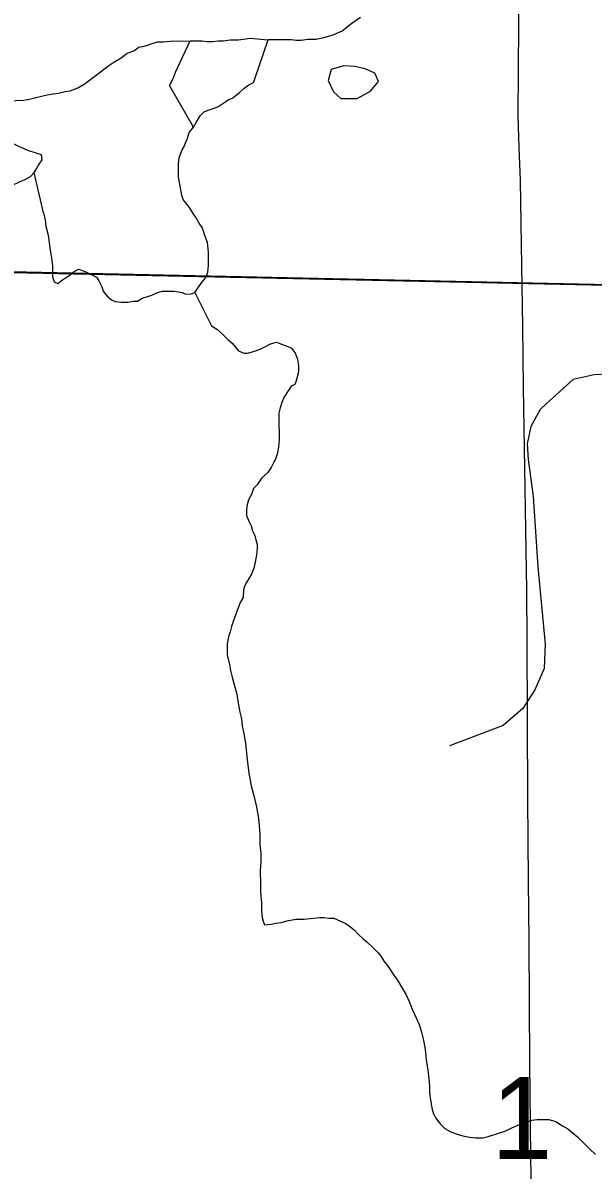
# Model space of a CAD drawing. Extents: x -6.1 to 38, y -7.7 to 22.
# Drawn here: x 2.439 to 2.73, y 14.598 to 15.183 of the extents above; entities that cross this region are included whole.
import ezdxf

# ---------------------------------------------------------------- set-up
doc = ezdxf.new("R2010")
doc.units = 0
for name, color, linetype in [('GM_X_Corporation', 7, 'Continuous'), ('GM_X_Major_River', 7, 'Continuous'), ('GM_X_Minor_Lake', 7, 'Continuous'), ('GM_X_Minor_River', 7, 'Continuous'), ('GM_X_Section_Text', 7, 'Continuous'), ('GM_X_Township_Road', 7, 'Continuous')]:
    doc.layers.add(name, color=color, linetype=linetype)

msp = doc.modelspace()

# ---------------------------------------------------------------- linework, layer by layer
at = {"layer": 'GM_X_Corporation'}
msp.add_lwpolyline([(2.1, 20.09414), (2.1, 15.06368), (2.27273, 15.0594), (2.84159, 15.04746)], dxfattribs=at)
for points in [[(2.23638, 16.06946), (3.24267, 16.03673), (3.24072, 15.94663), (3.23485, 15.60898), (3.22944, 15.30622), (3.22502, 15.03923), (2.22108, 15.06099)], [(2.1, 15.06368), (2.1, 14.1), (3.19219, 14.1), (3.19363, 14.14313), (3.20818, 14.53184), (3.22164, 14.89402), (3.22473, 15.03847), (3.13213, 15.04149), (2.88274, 15.0466), (2.84159, 15.04746), (2.27273, 15.0594)], [(2.22108, 15.06099), (3.22502, 15.03923), (3.195, 14.20385), (2.1728, 14.23687), (2.18735, 15.06192)]]:
    msp.add_lwpolyline(points, close=True, dxfattribs=at)
at = {"layer": 'GM_X_Major_River'}
for points in [[(2.61162, 15.18627), (2.6071, 15.18318), (2.6022, 15.17933), (2.5969, 15.177), (2.59274, 15.17581), (2.58894, 15.17501), (2.58476, 15.17497), (2.58134, 15.17456), (2.57868, 15.17453), (2.5764, 15.17489), (2.57412, 15.17487), (2.5707, 15.17483)], [(2.43155, 15.14368), (2.4395, 15.14411), (2.44253, 15.14451), (2.44518, 15.14529), (2.44858, 15.14607), (2.45161, 15.14685), (2.45464, 15.14725), (2.45729, 15.14765), (2.46069, 15.14843), (2.46334, 15.14883), (2.46712, 15.15037), (2.47051, 15.15229), (2.47315, 15.15421), (2.47654, 15.15688), (2.48257, 15.16148), (2.48559, 15.1634), (2.48936, 15.1657), (2.49238, 15.168), (2.49578, 15.16916), (2.49842, 15.17108), (2.50182, 15.17186), (2.50523, 15.17302), (2.50787, 15.1738), (2.5109, 15.17382), (2.51431, 15.17422), (2.52454, 15.17429), (2.52719, 15.17431), (2.5306, 15.17433), (2.53326, 15.17397), (2.53591, 15.17399), (2.53894, 15.17439), (2.54159, 15.17441), (2.545, 15.17481), (2.54916, 15.17484), (2.55181, 15.17524), (2.55522, 15.17564), (2.56436, 15.17477)], [(2.5707, 15.17483), (2.56766, 15.1748), (2.56436, 15.17477)]]:
    msp.add_lwpolyline(points, dxfattribs=at)
at = {"layer": 'GM_X_Minor_Lake'}
msp.add_line((2.60875, 15.16122), (2.60308, 15.16162), dxfattribs=at)
msp.add_lwpolyline([(2.60308, 15.16162), (2.59664, 15.15974), (2.59512, 15.15406), (2.59775, 15.14836), (2.60152, 15.14494), (2.60984, 15.14491), (2.61665, 15.14868), (2.62083, 15.1536), (2.61895, 15.15777), (2.61404, 15.16006), (2.60875, 15.16122)], dxfattribs=at)
at = {"layer": 'GM_X_Minor_River'}
for points in [[(2.44969, 15.08656), (2.4505, 15.08277), (2.45091, 15.07973), (2.45211, 15.07518), (2.45294, 15.06873), (2.45376, 15.06341), (2.45419, 15.05923), (2.45423, 15.05619), (2.45425, 15.05391), (2.45504, 15.05126), (2.45695, 15.05052), (2.45959, 15.05244), (2.46261, 15.05437), (2.46487, 15.0563), (2.46751, 15.05784), (2.47133, 15.05636), (2.47439, 15.05487), (2.47668, 15.05376), (2.47785, 15.05187), (2.4794, 15.04884), (2.48019, 15.04656), (2.48212, 15.04392), (2.48442, 15.04204), (2.48633, 15.0413), (2.48938, 15.04095), (2.4928, 15.04099), (2.49545, 15.0414), (2.49773, 15.04142), (2.5, 15.04296), (2.50492, 15.04453), (2.50757, 15.0457), (2.51022, 15.04648), (2.51402, 15.04652), (2.5163, 15.04654), (2.51859, 15.04619), (2.52049, 15.04583), (2.5224, 15.04508), (2.52506, 15.04511), (2.52695, 15.04589), (2.53032, 15.05087), (2.53257, 15.05355), (2.53368, 15.05622), (2.53402, 15.05965), (2.53397, 15.06345), (2.53394, 15.06649), (2.5335, 15.07143), (2.53232, 15.07446), (2.53154, 15.07673), (2.53075, 15.07901), (2.52921, 15.08127), (2.52765, 15.08392), (2.52611, 15.08618), (2.52456, 15.08883), (2.52301, 15.09071), (2.52108, 15.09336), (2.52029, 15.09563), (2.51867, 15.10474), (2.51863, 15.10778), (2.51859, 15.11158), (2.51893, 15.11463), (2.51967, 15.11654), (2.52041, 15.11844), (2.52153, 15.12036), (2.52227, 15.12226), (2.52301, 15.12417), (2.52411, 15.12761), (2.52636, 15.13029), (2.52785, 15.13297), (2.52971, 15.13602), (2.53197, 15.13833), (2.53537, 15.1395), (2.53878, 15.14068), (2.5418, 15.14261), (2.54406, 15.14415), (2.54633, 15.14531), (2.54972, 15.14801), (2.55198, 15.14994), (2.55462, 15.15186), (2.55689, 15.15302), (2.55762, 15.15493), (2.56436, 15.17477)], [(2.51395, 15.15146), (2.51507, 15.15337), (2.51617, 15.15604), (2.51728, 15.15871), (2.52454, 15.17429)], [(2.52636, 15.13029), (2.51395, 15.15146)], [(2.4127, 15.09646), (2.4165, 15.0965), (2.4203, 15.09692), (2.4241, 15.09733), (2.42826, 15.0989), (2.43357, 15.10047), (2.43734, 15.10241), (2.44037, 15.10358), (2.44301, 15.10513), (2.44489, 15.10705), (2.44601, 15.10896), (2.44713, 15.11087), (2.449, 15.11355), (2.44859, 15.11621), (2.44592, 15.11694), (2.44172, 15.11842), (2.43675, 15.12065), (2.43293, 15.12252), (2.43025, 15.12401), (2.42793, 15.12779), (2.4279, 15.12969), (2.42788, 15.13159), (2.4289, 15.14252)], [(2.44969, 15.08656), (2.44489, 15.10705)], [(2.52695, 15.04589), (2.53552, 15.02887), (2.53858, 15.027), (2.54127, 15.02436), (2.54396, 15.02172), (2.54626, 15.01985), (2.54781, 15.01796), (2.54935, 15.01608), (2.55202, 15.01496), (2.55392, 15.01498), (2.55696, 15.01577), (2.56036, 15.01695), (2.56339, 15.0185), (2.56565, 15.01966), (2.56868, 15.02045), (2.57174, 15.01934), (2.57441, 15.01822), (2.57632, 15.01749), (2.57825, 15.01484), (2.57943, 15.01181), (2.57985, 15.0084), (2.57989, 15.00536), (2.5788, 15.00078), (2.57806, 14.99887), (2.57617, 14.99809), (2.57505, 14.99618), (2.57243, 14.99235), (2.57132, 14.98968), (2.57059, 14.98701), (2.56986, 14.98434), (2.5699, 14.9813), (2.56993, 14.97826), (2.56998, 14.97446), (2.57002, 14.97104), (2.56969, 14.96685), (2.56897, 14.96342), (2.56824, 14.96076), (2.56712, 14.95884), (2.566, 14.95655), (2.56414, 14.95387), (2.56113, 14.95118), (2.55888, 14.94774), (2.557, 14.94581), (2.5559, 14.94276), (2.55441, 14.94009), (2.55368, 14.93742), (2.55333, 14.93513), (2.55336, 14.93209), (2.55454, 14.92906), (2.55571, 14.92679), (2.5565, 14.92414), (2.55766, 14.92187), (2.55807, 14.91959), (2.55886, 14.91732), (2.55888, 14.91542), (2.55854, 14.91199), (2.55782, 14.90818), (2.5571, 14.90513), (2.55599, 14.90208), (2.5545, 14.89979), (2.55338, 14.89787), (2.55226, 14.89596), (2.5519, 14.89406), (2.55157, 14.89025), (2.55008, 14.88758), (2.54676, 14.87842), (2.54566, 14.87536), (2.54493, 14.8727), (2.5442, 14.87003), (2.54348, 14.8666), (2.54352, 14.86318), (2.54354, 14.8609), (2.54395, 14.85862), (2.54474, 14.85597), (2.54516, 14.85293), (2.54596, 14.84951), (2.54714, 14.84572), (2.54834, 14.84079), (2.54915, 14.83624), (2.54997, 14.83169), (2.55077, 14.82827), (2.55119, 14.82447), (2.55199, 14.82068), (2.55281, 14.81574), (2.55367, 14.80739), (2.55451, 14.80055), (2.55572, 14.7941), (2.55731, 14.78841), (2.55851, 14.7831), (2.55932, 14.77855), (2.55976, 14.77399), (2.56019, 14.76905), (2.56025, 14.76411), (2.56068, 14.75955), (2.56073, 14.75537), (2.56041, 14.75043), (2.56049, 14.74396), (2.56054, 14.7394), (2.56097, 14.73446), (2.56103, 14.7299), (2.56144, 14.72686)], [(2.56144, 14.72686), (2.56185, 14.72497), (2.56263, 14.72307), (2.56604, 14.72349), (2.56832, 14.72389), (2.57098, 14.7243), (2.57401, 14.72508), (2.57856, 14.72589), (2.58274, 14.72593), (2.59072, 14.72677), (2.593, 14.72679), (2.59566, 14.72644), (2.59794, 14.72647), (2.60138, 14.72498), (2.60368, 14.72386), (2.60597, 14.72236), (2.60828, 14.72048), (2.61058, 14.71822), (2.61289, 14.71597), (2.61481, 14.71447), (2.61789, 14.71145), (2.62058, 14.70882), (2.62212, 14.70694), (2.62367, 14.70429), (2.62599, 14.70127), (2.62831, 14.69787), (2.63063, 14.69447), (2.63295, 14.69069), (2.63489, 14.68729), (2.63645, 14.68389), (2.63802, 14.6801), (2.63997, 14.67555), (2.64153, 14.67215), (2.64272, 14.66836), (2.64351, 14.66494), (2.64431, 14.66153), (2.64473, 14.65811), (2.64516, 14.65394), (2.64598, 14.649), (2.64641, 14.64444), (2.64684, 14.64065), (2.64688, 14.63722), (2.6473, 14.6338), (2.6477, 14.63153), (2.64811, 14.62887), (2.6489, 14.6266), (2.65045, 14.62395), (2.65238, 14.62131), (2.65469, 14.61905), (2.65737, 14.61756), (2.66042, 14.61645), (2.66386, 14.61534), (2.66729, 14.61462), (2.67033, 14.61426), (2.67413, 14.6143), (2.67678, 14.61509), (2.68588, 14.61784), (2.6889, 14.61939), (2.69155, 14.62056), (2.69382, 14.62172), (2.69647, 14.62251), (2.69912, 14.62329), (2.70177, 14.6237), (2.70482, 14.62373), (2.70786, 14.62376), (2.71129, 14.62265), (2.71474, 14.62041), (2.71742, 14.61891), (2.71972, 14.61704), (2.72241, 14.61478), (2.72548, 14.61177), (2.72856, 14.60876), (2.73163, 14.60575)]]:
    msp.add_lwpolyline(points, dxfattribs=at)
at = {"layer": 'GM_X_Township_Road'}
for points in [[(2.69895, 14.58691), (2.69866, 14.60411), (2.69837, 14.62131), (2.69814, 14.65237), (2.6979, 14.68344), (2.69767, 14.71451), (2.69743, 14.74558), (2.69727, 14.76654), (2.69711, 14.7875), (2.69676, 14.868), (2.6965, 14.89416), (2.69619, 14.91471), (2.69589, 14.93526), (2.6954, 14.96632), (2.69492, 14.99738), (2.69444, 15.02845), (2.69395, 15.05951), (2.69361, 15.08128), (2.69327, 15.10305), (2.6927, 15.11967), (2.69213, 15.13628), (2.69231, 15.15937), (2.69249, 15.18247), (2.6924, 15.19753)], [(2.88816, 15.04182), (2.88295, 15.04606), (2.87566, 15.05145), (2.86458, 15.05899), (2.86057, 15.063), (2.85491, 15.06489), (2.85043, 15.06441), (2.84548, 15.06041), (2.8418, 15.04692), (2.83841, 15.03635), (2.83416, 15.02292), (2.82897, 15.01513), (2.82143, 15.00877), (2.81389, 15.00405), (2.79997, 15.00028), (2.78536, 14.99887), (2.75942, 15.00287), (2.74174, 15.00429), (2.73089, 15.00382), (2.72028, 15.00146), (2.70649, 14.98901)], [(2.70649, 14.98901), (2.70331, 14.98613), (2.69859, 14.97741), (2.6967, 14.96869), (2.69718, 14.96067), (2.69977, 14.94181), (2.70213, 14.90574), (2.7059, 14.86636), (2.70543, 14.85386), (2.70071, 14.84302), (2.69458, 14.83359), (2.68444, 14.82486), (2.6571, 14.81449)]]:
    msp.add_lwpolyline(points, dxfattribs=at)

# ---------------------------------------------------------------- texts
at = {"layer": 'GM_X_Section_Text'}
msp.add_text('1', height=0.04186, rotation=0.00001, dxfattribs=at).set_placement((2.67844, 14.60351))

doc.saveas('drawing.dxf')
